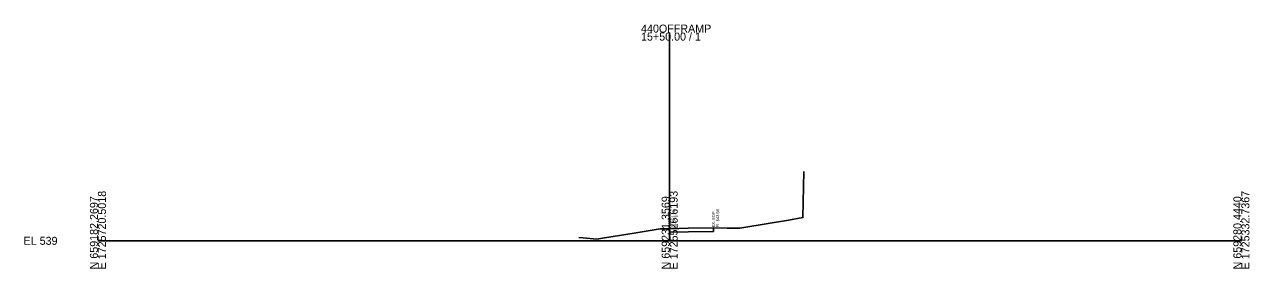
# Model space of a CAD drawing. Extents: x 1728898 to 1729326, y 661368 to 668397.
# Drawn here: x 1728897.8 to 1729326.3, y 662368.4 to 662453.8 of the extents above; entities that cross this region are included whole.
import ezdxf

# ---------------------------------------------------------------- set-up
doc = ezdxf.new("R2010")
doc.units = 0
for name, color, linetype in [('DESIGN - SHEET - Light Grid', 7, 'Continuous'), ('SURVEY - GROUND - Existing Pavement Layer', 7, 'Continuous'), ('SURVEY - GROUND - Existing Pavement Text', 7, 'Continuous'), ('SURVEY - GROUND - Top of Ground', 7, 'Continuous')]:
    doc.layers.add(name, color=color, linetype=linetype)

msp = doc.modelspace()

# ---------------------------------------------------------------- linework, layer by layer
at = {"layer": 'DESIGN - SHEET - Light Grid'}
for p, q in [((1729123.44, 662378.11), (1729123.44, 662450.98)), ((1728923.44, 662378.11), (1729123.44, 662378.11)), ((1729123.44, 662378.11), (1729323.44, 662378.11))]:
    msp.add_line(p, q, dxfattribs=at)
at = {"layer": 'SURVEY - GROUND - Existing Pavement Layer'}
for p, q in [((1729123.5, 662381.09), (1729129.92, 662381.23)), ((1729129.92, 662381.23), (1729138.76, 662381.42)), ((1729138.76, 662382.67), (1729138.76, 662381.42))]:
    msp.add_line(p, q, dxfattribs=at)
at = {"layer": 'SURVEY - GROUND - Top of Ground'}
msp.add_lwpolyline([(1729091.66, 662379.26), (1729093.13, 662379.13), (1729097.95, 662378.69), (1729099.97, 662379.02), (1729108.14, 662380.34), (1729111.74, 662380.88), (1729120.07, 662382.25), (1729120.56, 662382.27), (1729123.5, 662382.34), (1729129.92, 662382.48), (1729138.76, 662382.67), (1729143.55, 662382.57), (1729147.5, 662382.5), (1729147.99, 662382.57), (1729149.35, 662382.79), (1729164.97, 662385.38), (1729170.05, 662386.22), (1729170.35, 662402.4)], dxfattribs=at)

# ---------------------------------------------------------------- texts
at = {"layer": 'DESIGN - SHEET - Light Grid'}
for s, p in [('440OFFRAMP', (1729113.44, 662450.98)), ('15+50.00 / 1', (1729113.44, 662448.18)), ('EL 539', (1728897.44, 662376.71))]:
    msp.add_text(s, height=2.8, dxfattribs=at).set_placement(p)
for s, p in [('N 659182.2697', (1728923.44, 662368.11)), ('E 1725720.5018', (1728926.24, 662368.11)), ('N 659231.3569', (1729123.44, 662368.11)), ('E 1725526.6193', (1729126.24, 662368.11)), ('N 659280.4440', (1729323.44, 662368.11)), ('E 1725332.7367', (1729326.24, 662368.11))]:
    msp.add_text(s, height=2.8, rotation=90, dxfattribs=at).set_placement(p)
at = {"layer": 'SURVEY - GROUND - Existing Pavement Text'}
for s, p in [('EX. EOP', (1729124, 662382.54)), ('EL.543.24', (1729125.5, 662382.54)), ('EX. EOP', (1729139.26, 662382.87)), ('EL.543.56', (1729140.76, 662382.87))]:
    msp.add_text(s, height=1, rotation=90, dxfattribs=at).set_placement(p)

doc.saveas('drawing.dxf')
